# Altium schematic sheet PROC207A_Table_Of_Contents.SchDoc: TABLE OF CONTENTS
size 431 x 279 mm; Date: Not shown in title block; ApprovedBy: Not shown in title block; CheckedBy: Not shown in title block; Author: Not shown in title block; CompanyName: Not shown in title block; DrawnBy: Mistral; Engineer: Not shown in title block; Organization: Not shown in title block; Address1: Not shown in title block; Address2: Not shown in title block; Address3: Not shown in title block; Address4: Not shown in title block; DocumentNumber: 3; Revision: Use project parameter SCH_Rev; SheetNumber: 3; SheetTotal: 18; PageSetup: Record=PageOptions¦CenterHorizontal=True¦CenterVertical=True¦PrintScale=1.00¦XCorrection=1.00¦YCorrection=1.00¦PrintKind=0¦BorderSize=5000000¦LeftOffset=0¦BottomOffset=0¦Orientation=2¦PaperLength=1000¦PaperWidth=1000¦Scale=100¦PaperSource=15¦PrintQuality=600¦MediaType=1¦DitherType=10¦PaperKind=Letter¦PrintScaleMode=1
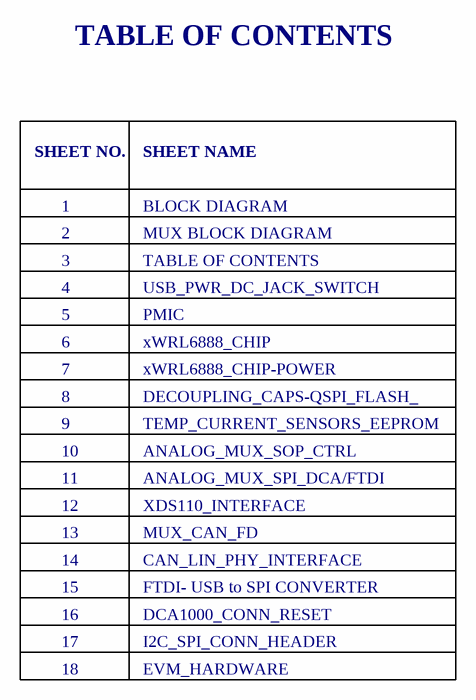
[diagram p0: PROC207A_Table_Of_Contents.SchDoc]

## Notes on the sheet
- TABLE OF CONTENTS
- SHEET NO.
- SHEET NAME
- 1
- 2
- 3
- BLOCK DIAGRAM
- MUX BLOCK DIAGRAM
- 4
- 5
- USB_PWR_DC_JACK_SWITCH
- PMIC
- 7
- 8
- 6
- DECOUPLING_CAPS-QSPI_FLASH_
- xWRL6888_CHIP
- xWRL6888_CHIP-POWER
- 10
- 9
- TEMP_CURRENT_SENSORS_EEPROM
- ANALOG_MUX_SOP_CTRL
- 11
- 12
- 13
- XDS110_INTERFACE
- ANALOG_MUX_SPI_DCA/FTDI
- MUX_CAN_FD
- 14
- 15
- CAN_LIN_PHY_INTERFACE
- FTDI- USB to SPI CONVERTER
- 16
- 17
- 18
- DCA1000_CONN_RESET
- I2C_SPI_CONN_HEADER
- EVM_HARDWARE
